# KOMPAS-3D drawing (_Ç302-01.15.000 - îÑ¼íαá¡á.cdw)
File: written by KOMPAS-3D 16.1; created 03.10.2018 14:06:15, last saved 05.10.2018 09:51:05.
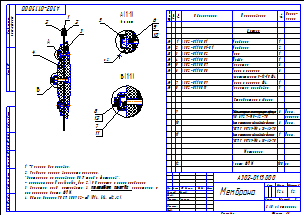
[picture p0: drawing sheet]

Sheet 1: A3, landscape

Title block, sheet 1: name: Мембрана; designation: А302-01.15.000; mass: 1,24; scale: 1:2; sheets: 1; organisation: ЗАО «Астерион»; sheet format: A3; stored path: \\192.168.87.28\Konstructor_doc\Мембранные насосы\Мембранный электропривод\А302-00.00.000 - ASTRA-302 (МЭ200)\3Д ПВХ\А302-01.15.000 - Мембрана.cdw; drawn by: Милов; technical control: Лучихин

Views: Вид 1, Местный разрез 1, Вид:2, Выносной элемент 3, Выносной элемент 4, Выносной элемент А, Выносной элемент, Выносной элемент Б
Referenced files in Z:\Мембранные насосы\Мембранный электропривод\А302-00.00.000 - ASTRA-302 (МЭ200)\3Д ПВХ\: А302-01.15.007 - Заглушка.m3d, А302-01.15.002 - Упор.m3d, А302-01.15.009 - Кольцо плоское Ф4.m3d, А302-01.15.003 - Шайба.m3d, А302-01.15.001-01- Мембрана.m3d, А302-01.15.011 - Заглушка резьбовая.m3d, А302-01.15.001 - Мембрана.m3d, А302-01.15.000 - Мембрана.a3d, А302-01.15.001 - Мембрана.cdw, А302-01.15.008 - Кольцо плоское уплотнительное 5-13-10 Ф4.cdw, А302-01.15.007 - Заглушка.cdw, А302-01.15.011 - Заглушка резьбовая.cdw, А302-01.15.008 - Кольцо плоское Ф4.m3d
Referenced files: graphic.tdp
Referenced files in C:\Program Files\ASCON\KOMPAS-3D V16\Libs\PartLib\DATA\vault\Methods\Kompas\3D\: PLib_Bolt_1_ISO_1100.m3d, PLib_Nut_ISO_1100.m3d
Referenced files in Z:\2 Стандартные изделия 3D\Гайки\DIN 6927\: Гайка шестигранная самостопорящаяся с фланцем DIN 6927-M5 - A2-70.m3d
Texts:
  *Размеры для справок.
  Разделку кромок выполнить согласно:
  "Инструкция по склеиванию ПВХ труб и фитингов".
  - расположение Konstructor_doc Z:\5 Оснастка и приспособления
  Заглушку поз. 8  установить в ГОЛОВНОЙ СБОРКЕ герметично с
  применением Ленты ФУМ.
  Общие допуски ГОСТ 30893.2-mK (H14, h14,  t2/2).
  Шайба
  Упор
  Болт с шестигранной головкой с фланцем
  ГОСТ Р  55739-М5 x 25-A2-70
  ГОСТ
  Нерж.
  Нержавеющая сталь
  Гайка шестигранная самостопорящаяся с фланцем
  DIN 6927-M5-A2-70
  Гайка
  шестигранная
  самостопорящаяся
  фланцем
  DIN
  насечки
  Нерж.насечки
  Кольцо плоское
  уплотнительное 5-13-10 Ф4
  Кольцо плоское  / уплотнительное 5-13-10 Ф4
  ГОСТ Р  55739-М8 x 30-A2-70
  Кольцо плоское Ф4
  Фланец с
  насечками
  Фланец снасечками
  Заглушка
  Заглушка резьбовая
  Лента ФУМ
  Лента
  ФУМ
  Лит-Масса-Масштаб
  Материал-Предприятие
  Title Specification
  Body Specification ( left align )
  Body Specificaton ( centered )
  Поз.
  Кол.
  Приме-
  чание
  Таблица спецификации
  Болт с шестигранной головкой с фланцем ГОСТ Р 55739 - М5 x 25 - A2-70
  Гайка шестигранная с фланцем ГОСТ Р ИСО 4161 - M5 - A2-70
  Гайка шестигранная самостопорящаяся с фланцем DIN 6927-M5 - A2-70
  Кольцо плоское уплотнительное 5-13-10 Ф4
  Болт с шестигранной головкой с фланцем ГОСТ Р 55739 - М8 x 30 - A2-70
Dimensions and other numbers on the sheet: 2; 1; 3; 4; 6 мест; 5; 6; 9; 10; 8; 12; 7; 11; 100; 1:2; 1,24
